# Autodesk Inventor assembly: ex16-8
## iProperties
Shininess: 64.0
Length Units: 11269
Angle Units: 11279
Time Units: 11290
Mass Units: 11283
Length Display Precision: 3
Angle Display Precision: 2
Compacted: True
Created: 2002-11
Part Number: ex16-8
Document SubType Name: Assembly
Designer: E. MOSS
Density: 0.0
Volumn: 0.0
Area: 0.0
PropertySet Name: Model Information
Control State: 0
Master: False
Checked Out: False
Author: E. MOSS
